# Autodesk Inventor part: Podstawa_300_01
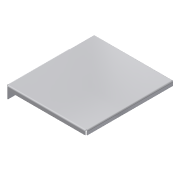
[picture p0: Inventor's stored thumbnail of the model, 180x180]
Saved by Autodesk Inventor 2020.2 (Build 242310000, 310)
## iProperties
Created: 2014-09
Part Number: Podstawa_300_01
Material: Ogólny
Document SubType Name: Konstrukcja blachowa
Designer: F.Stasiak
Density: 1 g/cm^3
Sheet Metal Rule: Domyślny_mm
Appearance: Śnieg
Catalog Web Link: www.expertbooks.pl
Manager: www.cadconsulting.pl
Company: Fabian Stasiak CAD Consulting
Author: F.Stasiak
Subject: Zbiór ćwiczeń. Autodesk Inventor 2020. Kurs Professional
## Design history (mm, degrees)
node "Powierzchnia1"
  sketch "Szkic1"
    geometry: L1 (0, 0)-(180, 0); L2 (180, 0)-(180, 200); L3 (180, 200)-(0, 200); L4 (0, 200)-(0, 0)
    constraints: 8 end point, 2 parallel, 1 horizontal, 1 perpendicular
    dimensions: "d0" = 180 distance of L1.start L1.end; "d1" = 200 distance of L1.end L2.end
node "Kołnierz1"
node "Kołnierz2"
node "Bryła1"
feature "Płyta1" dims "d25" = 1.5 (= Grubość)
sketch "Szkic2"
  geometry: L1 (0, -10)-(180, -10); L2 (180, -10)-(180, 0); 1 other entity
  constraints: 4 end point, 4 other
feature "Płyta2" dims "d3" = 1.5 (= SzerokośćGięciaPodcięcia), "d4" = 0.75 (= GłębokośćGięciaPodcięcia), "d5" = 3 (= MinimalnaPozostałość), "d6" = 1.5 (= PromieńGięcia), "d7" = 10, "d8" = 90 deg, "d9" = 1.5 (= PromieńGięcia), "d10" = 6 (= RozmiarPodcięciaNarożnika), "d11" = 1.5 (= Wielk_odstępu), "d12" = 1.5 (= Rozmiar_promienia_Jacobiego), "d25" = 1.5 (= Grubość), "OdstępPołączenia" = 0.01
feature "Gięcie1" dims "d3" = 1.5 (= SzerokośćGięciaPodcięcia), "d4" = 0.75 (= GłębokośćGięciaPodcięcia), "d5" = 3 (= MinimalnaPozostałość), "d6" = 1.5 (= PromieńGięcia), "d7" = 10, "d8" = 90 deg, "d9" = 1.5 (= PromieńGięcia), "d25" = 1.5 (= Grubość), "OdstępPołączenia" = 0.01
feature "Narożnik1" dims "d7" = 10, "d8" = 90 deg, "d10" = 6 (= RozmiarPodcięciaNarożnika), "d11" = 1.5 (= Wielk_odstępu), "d12" = 1.5 (= Rozmiar_promienia_Jacobiego)
sketch "Szkic3"
  geometry: L1 (194, 0)-(54, 0); L2 (54, 0)-(54, -27); L3 (54, -27)-(194, -27); L4 (194, -27)-(194, 0)
  constraints: 8 end point
feature "Płyta3" dims "d13" = 1.5 (= SzerokośćGięciaPodcięcia), "d14" = 0.75 (= GłębokośćGięciaPodcięcia), "d15" = 3 (= MinimalnaPozostałość), "d16" = 1.5 (= PromieńGięcia), "d17" = 140, "d18" = 0, "d19" = 30, "d20" = 90 deg, "d21" = 1.5 (= PromieńGięcia), "d22" = 6 (= RozmiarPodcięciaNarożnika), "d23" = 1.5 (= Wielk_odstępu), "d24" = 1.5 (= Rozmiar_promienia_Jacobiego), "d25" = 1.5 (= Grubość), "OdstępPołączenia" = 0.01
feature "Gięcie2" dims "d13" = 1.5 (= SzerokośćGięciaPodcięcia), "d14" = 0.75 (= GłębokośćGięciaPodcięcia), "d15" = 3 (= MinimalnaPozostałość), "d16" = 1.5 (= PromieńGięcia), "d19" = 30, "d20" = 90 deg, "d21" = 1.5 (= PromieńGięcia), "d25" = 1.5 (= Grubość), "OdstępPołączenia" = 0.01
feature "Narożnik2" dims "d19" = 30, "d20" = 90 deg, "d22" = 6 (= RozmiarPodcięciaNarożnika), "d23" = 1.5 (= Wielk_odstępu), "d24" = 1.5 (= Rozmiar_promienia_Jacobiego)
other parameters: "Grubość" = 1.5 (derived), "WspółczynnikK" = 4.4, "PromieńGięcia" = 1.5 (= Grubość), "SzerokośćGięciaPodcięcia" = 1.5 (= Grubość), "GłębokośćGięciaPodcięcia" = 0.75 (= 0.5 x Grubość), "RozmiarPodcięciaNarożnika" = 6 (= 4 x Grubość), "MinimalnaPozostałość" = 3 (= 2 x Grubość), "PromieńPrzejścia" = 1.5 (= PromieńGięcia), "Rozmiar_promienia_Jacobiego" = 1.5 (= PromieńGięcia), "Wielk_odstępu" = 1.5 (= Grubość), "d2" = 1.5 (= PromieńGięcia)
